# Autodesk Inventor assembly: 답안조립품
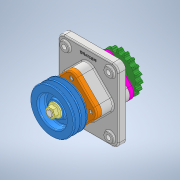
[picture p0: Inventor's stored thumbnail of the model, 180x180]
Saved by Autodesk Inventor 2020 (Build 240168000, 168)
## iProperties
Created: 2021-07
Part Number: 답안조립품
Document SubType Name: Assembly
Designer: Owner
Author: Owner
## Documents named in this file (16)
- C:\Users\Owner\Desktop\710707V1016\답안조립품.iam
- C:\Users\Owner\Desktop\710707V1016\본체.ipt
- C:\Users\Owner\Desktop\710707V1016\베어링 6206.ipt
- C:\Users\Owner\Desktop\710707V1016\볼트 M6.ipt
- C:\Users\Owner\Desktop\710707V1016\부시.ipt
- C:\Users\Owner\Desktop\710707V1016\오일실 30x42x8.ipt
- C:\Users\Owner\Desktop\710707V1016\오일실 30x45x8.ipt
- C:\Users\Owner\Desktop\710707V1016\체인 스프로킷.ipt
- C:\Users\Owner\Desktop\710707V1016\축.ipt
- C:\Users\Owner\Desktop\710707V1016\커버A.ipt
- C:\Users\Owner\Desktop\710707V1016\커버B.ipt
- C:\Users\Owner\Desktop\710707V1016\키 6x6x18.ipt
- C:\Users\Owner\Desktop\710707V1016\키 6x6x20.ipt
- C:\Users\Owner\Desktop\710707V1016\M16 너트.ipt
- C:\Users\Owner\Desktop\710707V1016\V-벨트풀리.ipt
- C:\Users\Owner\Desktop\710707V1016\멈춤나사 M4.ipt
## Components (3 placed, 2 different names)
1. M16 너트:1 — 각도:1
2. V-벨트풀리:1
3. M16 너트:2
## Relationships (1: Angle 1)
- 각도:1 [Angle]: M16 너트:1
